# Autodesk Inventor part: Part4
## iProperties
Shininess: 64.0
Length Units: 11269
Angle Units: 11279
Time Units: 11290
Mass Units: 11283
Length Display Precision: 3
Angle Display Precision: 2
Compacted: True
Part Number: Part4
Document SubType Name: Modeling
Created: 2004-08
Designer: John Blackburn
Manufacturer: Standard
Standards Organization: Custom
Density: 0.0
Volumn: 0.0
Area: 0.0
PropertySet Name: Model Information
Control State: 0
Master: False
Checked Out: False
Author: John Blackburn
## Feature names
1. Extrusion1
2. Extrusion2
3. Hole1
4. Hole3
5. Circular Pattern2
